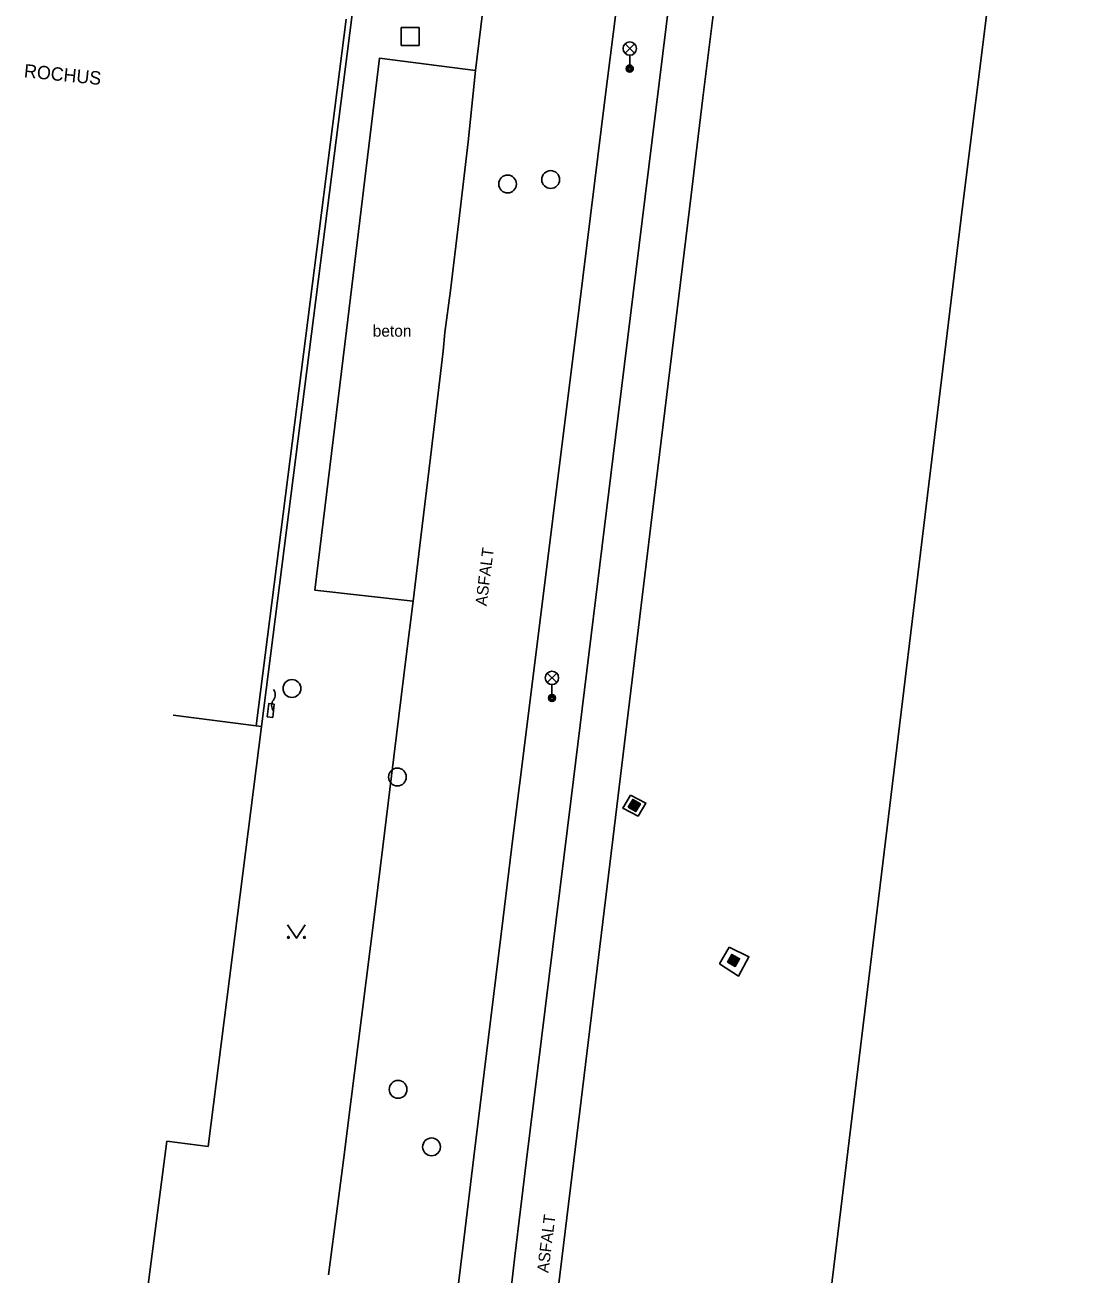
# Model space of a CAD drawing. Extents: x -541281 to -539153, y -1183881 to -1182141.
# Drawn here: x -540044.2 to -539985.7, y -1183321.5 to -1183251.3 of the extents above; entities that cross this region are included whole.
import ezdxf

# ---------------------------------------------------------------- set-up
doc = ezdxf.new("R2010")
doc.units = 0
for name, color, linetype in [('Vrstva 10', 7, 'Continuous'), ('Vrstva 11', 7, 'Continuous'), ('Vrstva 24', 7, 'Continuous'), ('Vrstva 25', 7, 'Continuous'), ('Vrstva 26', 7, 'Continuous'), ('Vrstva 27', 7, 'Continuous'), ('Vrstva 33', 7, 'Continuous'), ('Vrstva 36', 7, 'Continuous'), ('Vrstva 40', 7, 'Continuous'), ('Vrstva 41', 7, 'Continuous'), ('Vrstva 5', 7, 'Continuous'), ('Vrstva 7', 7, 'Continuous')]:
    doc.layers.add(name, color=color, linetype=linetype)

msp = doc.modelspace()

# ---------------------------------------------------------------- linework, layer by layer
at = {"layer": 'Vrstva 10'}
for p, q in [((-540018.075, -1183247.014), (-540018.93, -1183253.91)), ((-540018.93, -1183253.91), (-540019.342, -1183257.916)), ((-540012.26, -1183260.41), (-540013.107, -1183267.221)), ((-540013.107, -1183267.221), (-540016.08, -1183291.058)), ((-540020.737, -1183269.671), (-540021.454, -1183275.635)), ((-540021.454, -1183275.635), (-540021.996, -1183280.107)), ((-540022.815, -1183286.814), (-540023.64, -1183293.52)), ((-540016.08, -1183291.058), (-540016.82, -1183297.018)), ((-540016.82, -1183297.018), (-540017.374, -1183301.488)), ((-540024.566, -1183300.992), (-540025.328, -1183307.093)), ((-540017.374, -1183301.488), (-540018.2, -1183308.194)), ((-540018.2, -1183308.194), (-540019.02, -1183314.9)), ((-540019.02, -1183314.9), (-540019.642, -1183320.038)), ((-540019.642, -1183320.038), (-540020.182, -1183324.534))]:
    msp.add_line(p, q, dxfattribs=at)
for points in [[(-540011.043, -1183250.688), (-540011.654, -1183255.549), (-540012.26, -1183260.41)], [(-540019.342, -1183257.916), (-540019.867, -1183262.368), (-540020.329, -1183266.263)], [(-540020.329, -1183266.263), (-540020.64, -1183268.61), (-540020.737, -1183269.671)], [(-540021.996, -1183280.107), (-540022.43, -1183283.71)], [(-540022.43, -1183283.71), (-540022.815, -1183286.814)], [(-540023.64, -1183293.52), (-540024.133, -1183297.506), (-540024.566, -1183300.992)], [(-540025.328, -1183307.093), (-540025.905, -1183311.668), (-540026.343, -1183315.098)], [(-540026.343, -1183315.098), (-540026.673, -1183317.671), (-540027.173, -1183321.531)]]:
    msp.add_lwpolyline(points, dxfattribs=at)
at = {"layer": 'Vrstva 11'}
for p, q in [((-540006.65, -1183238.675), (-540009.39, -1183260.98)), ((-540009.39, -1183260.98), (-540011.053, -1183274.503)), ((-540007.901, -1183269.794), (-540006.82, -1183260.9)), ((-540008.979, -1183278.688), (-540007.901, -1183269.794)), ((-540011.053, -1183274.503), (-540013.552, -1183294.786)), ((-540011.134, -1183296.476), (-540008.979, -1183278.688)), ((-540013.552, -1183294.786), (-540016.05, -1183315.07)), ((-540012.574, -1183308.334), (-540011.134, -1183296.476)), ((-540013.4, -1183315.11), (-540012.574, -1183308.334)), ((-540014.434, -1183323.559), (-540013.4, -1183315.11))]:
    msp.add_line(p, q, dxfattribs=at)
for points in [[(-540006.15, -1183255.45), (-540005.534, -1183250.506), (-540004.989, -1183246.181)], [(-540022.43, -1183283.71), (-540027.94, -1183283.08), (-540026.17, -1183268.5), (-540024.31, -1183253.21), (-540018.93, -1183253.91)], [(-540006.82, -1183260.9), (-540006.476, -1183258.087), (-540006.15, -1183255.45)], [(-540016.05, -1183315.07), (-540016.392, -1183317.87), (-540016.708, -1183320.495), (-540017.001, -1183322.957)]]:
    msp.add_lwpolyline(points, dxfattribs=at)
at = {"layer": 'Vrstva 24'}
msp.add_lwpolyline([(-540030.615, -1183290.197), (-540030.31, -1183290.23), (-540030.23, -1183289.49), (-540030.535, -1183289.457), (-540030.615, -1183290.197)], dxfattribs=at)
for centre, start, end in [((-540030.67, -1183288.96), 323.1301, 36.8699), ((-540029.87, -1183289.56), 143.1301, 216.8699)]:
    msp.add_arc(centre, 0.5, start, end, dxfattribs=at)
at = {"layer": 'Vrstva 25'}
for points in [[(-540010.349, -1183295.269), (-540009.92, -1183295.525), (-540009.664, -1183295.095), (-540010.093, -1183294.84)], [(-540010.281, -1183295.252), (-540009.937, -1183295.456), (-540009.732, -1183295.113), (-540010.076, -1183294.908)], [(-540010.212, -1183295.234), (-540009.954, -1183295.388), (-540009.801, -1183295.13), (-540010.059, -1183294.977)], [(-540010.144, -1183295.217), (-540009.972, -1183295.319), (-540009.869, -1183295.148), (-540010.041, -1183295.045)], [(-540010.075, -1183295.2), (-540009.989, -1183295.251), (-540009.938, -1183295.165), (-540010.024, -1183295.114)], [(-540004.776, -1183303.974), (-540004.34, -1183304.218), (-540004.095, -1183303.782), (-540004.531, -1183303.538)], [(-540004.708, -1183303.954), (-540004.359, -1183304.15), (-540004.163, -1183303.802), (-540004.512, -1183303.606)], [(-540004.64, -1183303.935), (-540004.378, -1183304.082), (-540004.232, -1183303.821), (-540004.493, -1183303.674)], [(-540004.572, -1183303.916), (-540004.398, -1183304.014), (-540004.3, -1183303.84), (-540004.474, -1183303.742)], [(-540004.504, -1183303.897), (-540004.417, -1183303.946), (-540004.368, -1183303.859), (-540004.455, -1183303.81)]]:
    msp.add_lwpolyline(points, close=True, dxfattribs=at)
at = {"layer": 'Vrstva 26'}
msp.add_lwpolyline([(-540023.09, -1183252.5), (-540022.09, -1183252.5), (-540022.09, -1183251.5), (-540023.09, -1183251.5)], close=True, dxfattribs=at)
at = {"layer": 'Vrstva 27'}
for centre in [(-540017.12, -1183260.28), (-540014.7, -1183260.03), (-540029.23, -1183288.61), (-540023.308, -1183293.579), (-540023.27, -1183311.12), (-540021.39, -1183314.35)]:
    msp.add_circle(centre, 0.5, dxfattribs=at)
at = {"layer": 'Vrstva 33'}
for p, q in [((-540010.525, -1183252.94), (-540009.995, -1183252.41)), ((-540010.525, -1183252.41), (-540009.995, -1183252.94)), ((-540010.26, -1183253.05), (-540010.26, -1183253.8)), ((-540014.895, -1183288.28), (-540014.365, -1183287.75)), ((-540014.895, -1183287.75), (-540014.365, -1183288.28)), ((-540014.63, -1183288.39), (-540014.63, -1183289.14))]:
    msp.add_line(p, q, dxfattribs=at)
for centre, radius in [((-540010.26, -1183252.675), 0.375), ((-540010.26, -1183253.8), 0.2), ((-540010.26, -1183253.8), 0.145), ((-540010.26, -1183253.8), 0.0876), ((-540014.63, -1183288.015), 0.375), ((-540014.63, -1183289.14), 0.2), ((-540014.63, -1183289.14), 0.145), ((-540014.63, -1183289.14), 0.0876)]:
    msp.add_circle(centre, radius, dxfattribs=at)
at = {"layer": 'Vrstva 36'}
msp.add_lwpolyline([(-540029.48, -1183301.885), (-540028.98, -1183302.635), (-540028.48, -1183301.885)], dxfattribs=at)
for centre in [(-540029.43, -1183302.585), (-540028.53, -1183302.585)]:
    msp.add_circle(centre, 0.05, dxfattribs=at)
at = {"layer": 'Vrstva 5'}
for p, q in [((-540035.9, -1183290.111), (-540031.238, -1183290.702)), ((-540033.93, -1183314.32), (-540030.94, -1183290.74)), ((-540031.238, -1183290.702), (-540030.94, -1183290.74)), ((-540039.513, -1183338.925), (-540036.261, -1183314.024)), ((-540036.261, -1183314.024), (-540033.93, -1183314.32))]:
    msp.add_line(p, q, dxfattribs=at)
at = {"layer": 'Vrstva 7'}
for p, q in [((-539991.57, -1183261.56), (-539985.65, -1183214)), ((-540030.94, -1183290.74), (-540025.85, -1183250.76)), ((-540026.186, -1183251.027), (-540031.238, -1183290.702)), ((-539997.69, -1183311.98), (-539991.57, -1183261.56)), ((-540004.06, -1183363.91), (-539997.69, -1183311.98))]:
    msp.add_line(p, q, dxfattribs=at)
for points in [[(-540010.22, -1183294.59), (-540009.36, -1183295.04), (-540009.79, -1183295.77), (-540010.65, -1183295.32), (-540010.22, -1183294.59)], [(-540004.68, -1183303.13), (-540005.22, -1183304.07), (-540004.16, -1183304.76), (-540003.57, -1183303.67), (-540004.68, -1183303.13)]]:
    msp.add_lwpolyline(points, dxfattribs=at)

# ---------------------------------------------------------------- texts
at = {"layer": 'Vrstva 40'}
msp.add_text('beton', height=0.65, dxfattribs=at).set_placement((-540024.694, -1183268.853))
for rotation, p in [(82.88654, (-540018.297, -1183284.004)), (83.02521, (-540014.83, -1183321.448))]:
    msp.add_text('ASFALT', height=0.65, rotation=rotation, dxfattribs=at).set_placement(p)
at = {"layer": 'Vrstva 41'}
msp.add_text('ROCHUS', height=0.75, rotation=354.18602, dxfattribs=at).set_placement((-540044.304, -1183254.284))

doc.saveas('drawing.dxf')
